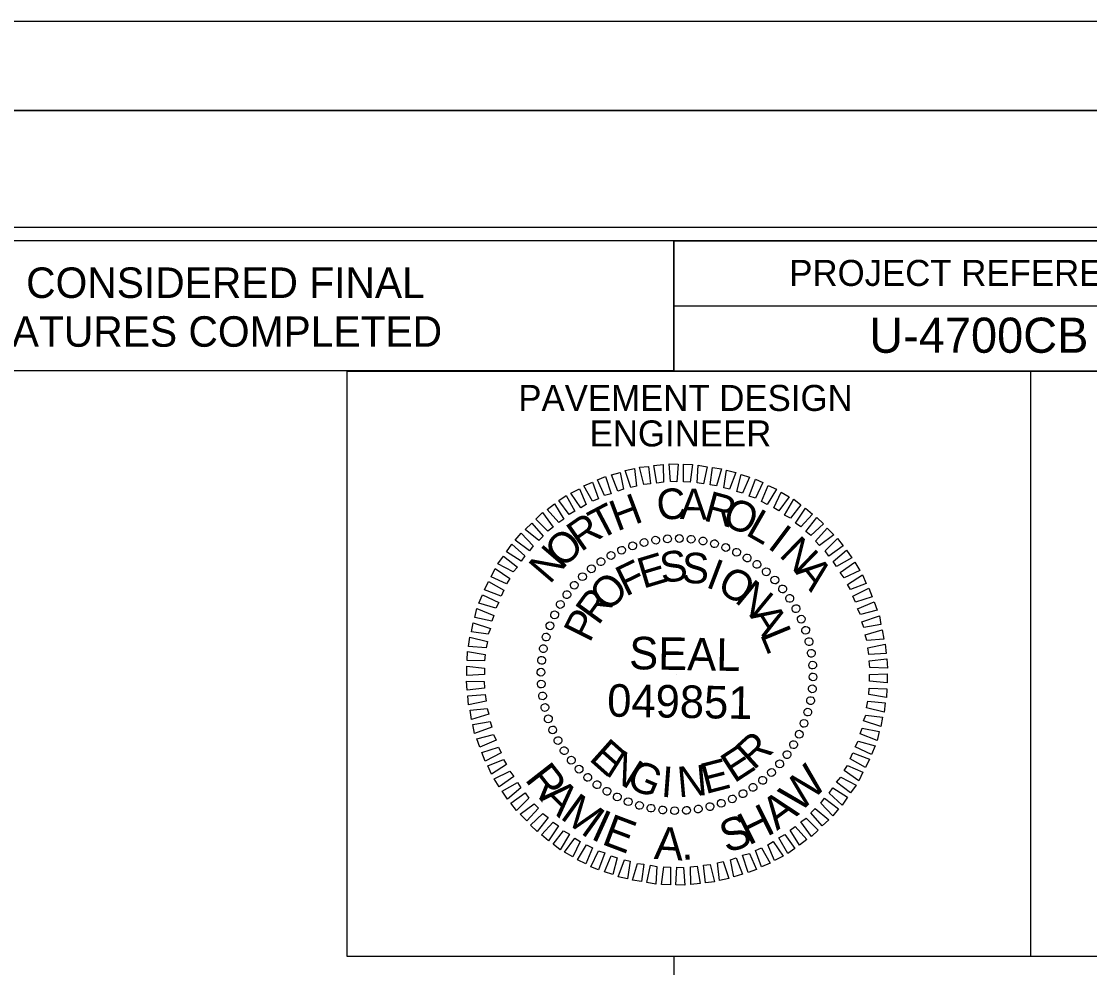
# Model space of a CAD drawing. Extents: x 2294455 to 2294795, y 719276 to 719941.
# Drawn here: x 2294722.83 to 2294763.9, y 719682.39 to 719718.76 of the extents above; entities that cross this region are included whole.
import ezdxf

# ---------------------------------------------------------------- set-up
doc = ezdxf.new("R2010")
doc.units = 0
for name, color, linetype in [('Default', 7, 'Continuous'), ('Old_Level_1', 7, 'Continuous'), ('Old_Level_2', 7, 'Continuous'), ('Sheet Data Field CELL', 7, 'Continuous'), ('Sheet Plan CELL', 7, 'Continuous'), ('Sheet Plot Border Inside CELL', 7, 'Continuous'), ('Sheet Plot Border Outside CELL', 7, 'Continuous'), ('Sheet Sticker Exception Certification CELL', 7, 'Continuous'), ('Sheet Typical CELL', 7, 'Continuous')]:
    doc.layers.add(name, color=color, linetype=linetype)

msp = doc.modelspace()

# ---------------------------------------------------------------- linework, layer by layer
at = {"layer": 'Default'}
msp.add_lwpolyline([(2294454.524, 719715.329), (2294794.524, 719715.329), (2294794.524, 719495.329), (2294454.524, 719495.329)], close=True, dxfattribs=at)
at = {"layer": 'Old_Level_1'}
msp.add_lwpolyline([(2294747.917, 719675.6), (2294787.924, 719675.6), (2294787.924, 719682.819), (2294747.917, 719682.819)], close=True, dxfattribs=at)
at = {"layer": 'Old_Level_2'}
for p, q in [((2294746.326, 719698.605), (2294746.326, 719698.605)), ((2294746.764, 719698.73), (2294746.764, 719698.73)), ((2294747.223, 719698.814), (2294747.223, 719698.814)), ((2294747.671, 719698.876), (2294747.671, 719698.876)), ((2294748.13, 719698.887), (2294748.13, 719698.887)), ((2294748.589, 719698.856), (2294748.589, 719698.856)), ((2294749.037, 719698.783), (2294749.037, 719698.783)), ((2294749.476, 719698.689), (2294749.476, 719698.689)), ((2294749.914, 719698.543), (2294749.914, 719698.543)), ((2294745.502, 719698.23), (2294745.502, 719698.23)), ((2294745.909, 719698.438), (2294745.909, 719698.438)), ((2294750.331, 719698.355), (2294750.331, 719698.355)), ((2294750.737, 719698.146), (2294750.737, 719698.146)), ((2294744.741, 719697.729), (2294744.741, 719697.729)), ((2294745.106, 719697.99), (2294745.106, 719697.99)), ((2294751.113, 719697.886), (2294751.113, 719697.886)), ((2294744.396, 719697.416), (2294744.396, 719697.416)), ((2294751.478, 719697.604), (2294751.478, 719697.604)), ((2294744.083, 719697.093), (2294744.083, 719697.093)), ((2294751.801, 719697.291), (2294751.801, 719697.291)), ((2294752.114, 719696.947), (2294752.114, 719696.947)), ((2294743.802, 719696.728), (2294743.802, 719696.728)), ((2294752.375, 719696.582), (2294752.375, 719696.582)), ((2294743.541, 719696.352), (2294743.541, 719696.352)), ((2294752.615, 719696.186), (2294752.615, 719696.186)), ((2294743.333, 719695.946), (2294743.333, 719695.946)), ((2294752.823, 719695.779), (2294752.823, 719695.779)), ((2294743.145, 719695.529), (2294743.145, 719695.529)), ((2294752.99, 719695.362), (2294752.99, 719695.362)), ((2294742.999, 719695.091), (2294742.999, 719695.091)), ((2294753.115, 719694.924), (2294753.115, 719694.924)), ((2294742.905, 719694.652), (2294742.905, 719694.652)), ((2294753.199, 719694.465), (2294753.199, 719694.465)), ((2294742.832, 719694.204), (2294742.832, 719694.204)), ((2294753.261, 719694.016), (2294753.261, 719694.016)), ((2294742.801, 719693.745), (2294742.801, 719693.745)), ((2294748.036, 719693.651), (2294748.036, 719693.651)), ((2294742.811, 719693.286), (2294742.811, 719693.286)), ((2294753.272, 719693.557), (2294753.272, 719693.557)), ((2294742.874, 719692.838), (2294742.874, 719692.838)), ((2294753.241, 719693.098), (2294753.241, 719693.098)), ((2294742.957, 719692.379), (2294742.957, 719692.379)), ((2294753.168, 719692.65), (2294753.168, 719692.65)), ((2294753.074, 719692.212), (2294753.074, 719692.212)), ((2294743.082, 719691.941), (2294743.082, 719691.941)), ((2294752.928, 719691.774), (2294752.928, 719691.774)), ((2294743.249, 719691.524), (2294743.249, 719691.524)), ((2294752.74, 719691.357), (2294752.74, 719691.357)), ((2294743.458, 719691.117), (2294743.458, 719691.117)), ((2294752.531, 719690.95), (2294752.531, 719690.95)), ((2294743.698, 719690.721), (2294743.698, 719690.721)), ((2294743.958, 719690.356), (2294743.958, 719690.356)), ((2294752.271, 719690.575), (2294752.271, 719690.575)), ((2294744.271, 719690.011), (2294744.271, 719690.011)), ((2294751.989, 719690.21), (2294751.989, 719690.21)), ((2294744.595, 719689.698), (2294744.595, 719689.698)), ((2294751.332, 719689.573), (2294751.332, 719689.573)), ((2294751.676, 719689.886), (2294751.676, 719689.886)), ((2294744.96, 719689.417), (2294744.96, 719689.417)), ((2294745.335, 719689.156), (2294745.335, 719689.156)), ((2294750.967, 719689.313), (2294750.967, 719689.313)), ((2294745.742, 719688.948), (2294745.742, 719688.948)), ((2294746.159, 719688.76), (2294746.159, 719688.76)), ((2294749.747, 719688.697), (2294749.747, 719688.697)), ((2294750.164, 719688.864), (2294750.164, 719688.864)), ((2294750.571, 719689.073), (2294750.571, 719689.073)), ((2294746.597, 719688.614), (2294746.597, 719688.614)), ((2294747.035, 719688.52), (2294747.035, 719688.52)), ((2294747.483, 719688.447), (2294747.483, 719688.447)), ((2294747.942, 719688.416), (2294747.942, 719688.416)), ((2294748.401, 719688.426), (2294748.401, 719688.426)), ((2294748.85, 719688.489), (2294748.85, 719688.489)), ((2294749.309, 719688.572), (2294749.309, 719688.572))]:
    msp.add_line(p, q, dxfattribs=at)
for points in [[(2294745.763, 719700.702), (2294745.523, 719701.327), (2294745.846, 719701.421), (2294745.982, 719700.775)], [(2294746.263, 719700.837), (2294746.044, 719701.494), (2294746.399, 719701.567), (2294746.482, 719700.889)], [(2294746.764, 719700.952), (2294746.597, 719701.619), (2294746.941, 719701.651), (2294747.014, 719700.983)], [(2294747.264, 719701.014), (2294747.15, 719701.682), (2294747.504, 719701.724), (2294747.515, 719701.046)], [(2294747.786, 719701.067), (2294747.734, 719701.745), (2294748.078, 719701.734), (2294748.036, 719701.056)], [(2294748.287, 719701.056), (2294748.287, 719701.734), (2294748.631, 719701.724), (2294748.537, 719701.046)], [(2294748.808, 719701.025), (2294748.85, 719701.703), (2294749.194, 719701.64), (2294749.058, 719700.983)], [(2294749.309, 719700.941), (2294749.402, 719701.609), (2294749.747, 719701.557), (2294749.559, 719700.91)], [(2294749.841, 719700.827), (2294749.945, 719701.505), (2294750.299, 719701.421), (2294750.06, 719700.775)], [(2294744.793, 719700.316), (2294744.459, 719700.9), (2294744.782, 719701.046), (2294745.022, 719700.41)], [(2294745.252, 719700.535), (2294744.98, 719701.14), (2294745.293, 719701.265), (2294745.512, 719700.597)], [(2294750.341, 719700.691), (2294750.498, 719701.338), (2294750.821, 719701.233), (2294750.56, 719700.618)], [(2294750.81, 719700.503), (2294751.05, 719701.16), (2294751.342, 719701.035), (2294751.05, 719700.43)], [(2294744.344, 719700.065), (2294743.958, 719700.629), (2294744.282, 719700.795), (2294744.542, 719700.191)], [(2294751.28, 719700.305), (2294751.541, 719700.921), (2294751.864, 719700.775), (2294751.509, 719700.191)], [(2294751.76, 719700.065), (2294752.041, 719700.66), (2294752.354, 719700.483), (2294751.958, 719699.94)], [(2294743.489, 719699.492), (2294743.041, 719699.992), (2294743.322, 719700.211), (2294743.687, 719699.627)], [(2294743.885, 719699.805), (2294743.499, 719700.337), (2294743.771, 719700.535), (2294744.115, 719699.93)], [(2294752.166, 719699.784), (2294752.531, 719700.389), (2294752.803, 719700.17), (2294752.396, 719699.659)], [(2294743.072, 719699.168), (2294742.613, 719699.627), (2294742.863, 719699.878), (2294743.27, 719699.314)], [(2294752.594, 719699.471), (2294752.98, 719700.045), (2294753.251, 719699.815), (2294752.792, 719699.325)], [(2294742.728, 719698.803), (2294742.196, 719699.231), (2294742.456, 719699.471), (2294742.895, 719698.97)], [(2294752.99, 719699.148), (2294753.418, 719699.69), (2294753.668, 719699.44), (2294753.188, 719698.991)], [(2294742.363, 719698.407), (2294741.82, 719698.814), (2294742.05, 719699.085), (2294742.509, 719698.595)], [(2294753.366, 719698.783), (2294753.814, 719699.273), (2294754.064, 719699.022), (2294753.522, 719698.616)], [(2294742.05, 719698.011), (2294741.487, 719698.365), (2294741.685, 719698.668), (2294742.185, 719698.209)], [(2294753.731, 719698.407), (2294754.21, 719698.876), (2294754.429, 719698.595), (2294753.877, 719698.198)], [(2294741.737, 719697.594), (2294741.153, 719697.906), (2294741.361, 719698.198), (2294741.904, 719697.781)], [(2294754.044, 719698), (2294754.555, 719698.438), (2294754.753, 719698.136), (2294754.169, 719697.802)], [(2294741.487, 719697.145), (2294740.892, 719697.406), (2294741.048, 719697.729), (2294741.612, 719697.343)], [(2294754.315, 719697.573), (2294754.868, 719697.969), (2294755.066, 719697.656), (2294754.461, 719697.364)], [(2294754.586, 719697.114), (2294755.17, 719697.479), (2294755.306, 719697.156), (2294754.711, 719696.916)], [(2294741.278, 719696.665), (2294740.631, 719696.905), (2294740.788, 719697.229), (2294741.382, 719696.895)], [(2294754.795, 719696.665), (2294755.41, 719696.978), (2294755.545, 719696.644), (2294754.899, 719696.436)], [(2294741.069, 719696.206), (2294740.423, 719696.394), (2294740.558, 719696.717), (2294741.184, 719696.425)], [(2294740.913, 719695.706), (2294740.266, 719695.841), (2294740.339, 719696.186), (2294740.996, 719695.925)], [(2294754.982, 719696.175), (2294755.618, 719696.446), (2294755.733, 719696.123), (2294755.087, 719695.956)], [(2294755.149, 719695.675), (2294755.817, 719695.914), (2294755.879, 719695.57), (2294755.222, 719695.456)], [(2294740.777, 719695.205), (2294740.131, 719695.289), (2294740.204, 719695.643), (2294740.861, 719695.424)], [(2294755.274, 719695.174), (2294755.931, 719695.372), (2294755.994, 719695.017), (2294755.337, 719694.955)], [(2294740.694, 719694.673), (2294740.026, 719694.736), (2294740.068, 719695.091), (2294740.746, 719694.924)], [(2294740.642, 719694.173), (2294739.964, 719694.194), (2294739.985, 719694.538), (2294740.663, 719694.423)], [(2294755.368, 719694.673), (2294756.046, 719694.819), (2294756.077, 719694.465), (2294755.41, 719694.423)], [(2294755.431, 719694.173), (2294756.109, 719694.256), (2294756.13, 719693.902), (2294755.452, 719693.922)], [(2294740.631, 719693.651), (2294739.953, 719693.62), (2294739.953, 719693.975), (2294740.631, 719693.902)], [(2294755.441, 719693.651), (2294756.119, 719693.683), (2294756.119, 719693.328), (2294755.441, 719693.401)], [(2294740.642, 719693.13), (2294739.964, 719693.046), (2294739.943, 719693.401), (2294740.621, 719693.38)], [(2294740.704, 719692.629), (2294740.026, 719692.483), (2294739.995, 719692.838), (2294740.663, 719692.879)], [(2294755.431, 719693.13), (2294756.109, 719693.109), (2294756.088, 719692.765), (2294755.41, 719692.879)], [(2294755.379, 719692.629), (2294756.046, 719692.567), (2294756.004, 719692.212), (2294755.326, 719692.379)], [(2294740.798, 719692.129), (2294740.141, 719691.93), (2294740.079, 719692.285), (2294740.736, 719692.348)], [(2294755.295, 719692.097), (2294755.942, 719692.014), (2294755.869, 719691.659), (2294755.212, 719691.878)], [(2294740.923, 719691.628), (2294740.256, 719691.388), (2294740.193, 719691.732), (2294740.85, 719691.847)], [(2294755.16, 719691.597), (2294755.806, 719691.461), (2294755.733, 719691.117), (2294755.076, 719691.378)], [(2294741.09, 719691.127), (2294740.454, 719690.856), (2294740.339, 719691.179), (2294740.986, 719691.346)], [(2294741.278, 719690.637), (2294740.663, 719690.324), (2294740.527, 719690.658), (2294741.174, 719690.867)], [(2294755.003, 719691.096), (2294755.65, 719690.908), (2294755.514, 719690.585), (2294754.888, 719690.877)], [(2294741.487, 719690.189), (2294740.902, 719689.824), (2294740.767, 719690.147), (2294741.361, 719690.387)], [(2294754.795, 719690.637), (2294755.441, 719690.397), (2294755.285, 719690.074), (2294754.69, 719690.408)], [(2294741.758, 719689.73), (2294741.205, 719689.333), (2294741.007, 719689.646), (2294741.612, 719689.938)], [(2294754.586, 719690.157), (2294755.18, 719689.897), (2294755.024, 719689.573), (2294754.461, 719689.959)], [(2294742.029, 719689.302), (2294741.518, 719688.864), (2294741.32, 719689.167), (2294741.904, 719689.5)], [(2294754.336, 719689.709), (2294754.92, 719689.396), (2294754.711, 719689.104), (2294754.169, 719689.521)], [(2294742.342, 719688.895), (2294741.862, 719688.426), (2294741.643, 719688.708), (2294742.196, 719689.104)], [(2294754.023, 719689.292), (2294754.586, 719688.937), (2294754.388, 719688.635), (2294753.887, 719689.094)], [(2294742.707, 719688.52), (2294742.258, 719688.03), (2294742.008, 719688.28), (2294742.55, 719688.687)], [(2294753.71, 719688.895), (2294754.252, 719688.489), (2294754.023, 719688.217), (2294753.564, 719688.708)], [(2294743.082, 719688.155), (2294742.655, 719687.613), (2294742.404, 719687.863), (2294742.884, 719688.311)], [(2294753.345, 719688.499), (2294753.877, 719688.071), (2294753.616, 719687.832), (2294753.178, 719688.332)], [(2294743.479, 719687.832), (2294743.093, 719687.258), (2294742.822, 719687.487), (2294743.28, 719687.978)], [(2294753.001, 719688.134), (2294753.46, 719687.675), (2294753.209, 719687.425), (2294752.803, 719687.988)], [(2294743.906, 719687.519), (2294743.541, 719686.914), (2294743.27, 719687.133), (2294743.677, 719687.644)], [(2294752.187, 719687.498), (2294752.573, 719686.966), (2294752.302, 719686.768), (2294751.958, 719687.373)], [(2294752.583, 719687.811), (2294753.032, 719687.31), (2294752.75, 719687.091), (2294752.385, 719687.675)], [(2294744.313, 719687.237), (2294744.031, 719686.643), (2294743.718, 719686.82), (2294744.115, 719687.362)], [(2294744.793, 719686.997), (2294744.532, 719686.382), (2294744.209, 719686.528), (2294744.563, 719687.112)], [(2294751.728, 719687.237), (2294752.114, 719686.674), (2294751.791, 719686.507), (2294751.53, 719687.112)], [(2294745.262, 719686.799), (2294745.022, 719686.142), (2294744.73, 719686.267), (2294745.022, 719686.872)], [(2294745.731, 719686.611), (2294745.575, 719685.965), (2294745.252, 719686.069), (2294745.512, 719686.684)], [(2294750.821, 719686.768), (2294751.092, 719686.163), (2294750.779, 719686.038), (2294750.56, 719686.705)], [(2294751.28, 719686.987), (2294751.614, 719686.403), (2294751.29, 719686.257), (2294751.05, 719686.893)], [(2294746.232, 719686.476), (2294746.128, 719685.798), (2294745.773, 719685.881), (2294746.013, 719686.528)], [(2294746.764, 719686.361), (2294746.67, 719685.694), (2294746.326, 719685.746), (2294746.514, 719686.392)], [(2294747.264, 719686.278), (2294747.223, 719685.6), (2294746.879, 719685.662), (2294747.014, 719686.319)], [(2294747.786, 719686.246), (2294747.786, 719685.568), (2294747.442, 719685.579), (2294747.536, 719686.257)], [(2294748.287, 719686.236), (2294748.339, 719685.558), (2294747.995, 719685.568), (2294748.036, 719686.246)], [(2294748.808, 719686.288), (2294748.923, 719685.621), (2294748.568, 719685.579), (2294748.558, 719686.257)], [(2294749.309, 719686.351), (2294749.476, 719685.683), (2294749.131, 719685.652), (2294749.058, 719686.319)], [(2294749.809, 719686.465), (2294750.028, 719685.808), (2294749.674, 719685.735), (2294749.59, 719686.413)], [(2294750.31, 719686.601), (2294750.55, 719685.975), (2294750.226, 719685.881), (2294750.091, 719686.528)]]:
    msp.add_lwpolyline(points, close=True, dxfattribs=at)
for centre, major_axis in [((2294747.218, 719698.818), (-0.023, 0.148)), ((2294747.671, 719698.87), (-0.01, 0.15)), ((2294748.128, 719698.882), (0.003, 0.15)), ((2294748.583, 719698.854), (0.016, 0.149)), ((2294749.034, 719698.787), (0.029, 0.147)), ((2294745.908, 719698.43), (-0.061, 0.137)), ((2294746.333, 719698.598), (-0.049, 0.142)), ((2294746.771, 719698.727), (-0.036, 0.146)), ((2294749.478, 719698.68), (0.041, 0.144)), ((2294749.911, 719698.535), (0.054, 0.14)), ((2294745.111, 719697.988), (-0.084, 0.125)), ((2294745.5, 719698.227), (-0.073, 0.131)), ((2294750.33, 719698.353), (0.066, 0.135)), ((2294750.731, 719698.135), (0.077, 0.129)), ((2294744.744, 719697.717), (-0.095, 0.117)), ((2294751.111, 719697.884), (0.088, 0.122)), ((2294751.468, 719697.599), (0.099, 0.113)), ((2294744.402, 719697.414), (-0.104, 0.108)), ((2294751.799, 719697.285), (0.108, 0.104)), ((2294743.804, 719696.726), (-0.122, 0.088)), ((2294744.088, 719697.083), (-0.113, 0.099)), ((2294752.102, 719696.943), (0.117, 0.095)), ((2294743.552, 719696.346), (-0.129, 0.077)), ((2294752.373, 719696.577), (0.125, 0.084)), ((2294743.334, 719695.945), (-0.135, 0.066)), ((2294752.612, 719696.187), (0.131, 0.073)), ((2294743.152, 719695.526), (-0.14, 0.054)), ((2294752.815, 719695.779), (0.137, 0.061)), ((2294743.007, 719695.093), (-0.144, 0.041)), ((2294752.983, 719695.354), (0.142, 0.049)), ((2294753.112, 719694.917), (0.146, 0.036)), ((2294742.901, 719694.649), (-0.147, 0.029)), ((2294753.203, 719694.47), (0.148, 0.023)), ((2294742.833, 719694.198), (-0.149, 0.016)), ((2294753.255, 719694.016), (0.15, 0.01)), ((2294742.806, 719693.743), (-0.15, 0.003)), ((2294753.267, 719693.56), (0.15, -0.003)), ((2294742.818, 719693.286), (-0.15, -0.01)), ((2294753.239, 719693.104), (0.149, -0.016)), ((2294742.869, 719692.833), (-0.148, -0.023)), ((2294753.172, 719692.653), (0.147, -0.029)), ((2294742.96, 719692.386), (-0.146, -0.036)), ((2294753.065, 719692.209), (0.144, -0.041)), ((2294743.09, 719691.948), (-0.142, -0.049)), ((2294743.257, 719691.523), (-0.137, -0.061)), ((2294752.92, 719691.776), (0.14, -0.054)), ((2294743.461, 719691.115), (-0.131, -0.073)), ((2294752.738, 719691.358), (0.135, -0.066)), ((2294743.699, 719690.726), (-0.125, -0.084)), ((2294752.269, 719690.576), (0.122, -0.088)), ((2294752.52, 719690.957), (0.129, -0.077)), ((2294743.971, 719690.359), (-0.117, -0.095)), ((2294751.984, 719690.219), (0.113, -0.099)), ((2294744.273, 719690.017), (-0.108, -0.104)), ((2294751.67, 719689.888), (0.104, -0.108)), ((2294744.604, 719689.703), (-0.099, -0.113)), ((2294744.961, 719689.419), (-0.088, -0.122)), ((2294751.328, 719689.586), (0.095, -0.117)), ((2294745.342, 719689.167), (-0.077, -0.129)), ((2294745.743, 719688.949), (-0.066, -0.135)), ((2294750.572, 719689.076), (0.073, -0.131)), ((2294750.962, 719689.314), (0.084, -0.125)), ((2294746.161, 719688.767), (-0.054, -0.14)), ((2294746.594, 719688.622), (-0.041, -0.144)), ((2294747.038, 719688.516), (-0.029, -0.147)), ((2294749.302, 719688.575), (0.036, -0.146)), ((2294749.739, 719688.705), (0.049, -0.142)), ((2294750.164, 719688.872), (0.061, -0.137)), ((2294747.489, 719688.448), (-0.016, -0.149)), ((2294747.945, 719688.421), (-0.003, -0.15)), ((2294748.401, 719688.433), (0.01, -0.15)), ((2294748.855, 719688.484), (0.023, -0.148))]:
    msp.add_ellipse(centre, major_axis=major_axis, ratio=0.999708, dxfattribs=at)
at = {"layer": 'Sheet Plan CELL'}
for points in [[(2294761.64, 719682.819), (2294735.355, 719682.819), (2294735.355, 719705.319), (2294761.64, 719705.319)], [(2294787.924, 719682.819), (2294761.64, 719682.819), (2294761.64, 719705.319), (2294787.924, 719705.319)]]:
    msp.add_lwpolyline(points, dxfattribs=at)
at = {"layer": 'Sheet Plot Border Inside CELL'}
msp.add_lwpolyline([(2294790.424, 719710.839), (2294457.124, 719710.839), (2294457.124, 719499.819), (2294790.424, 719499.819)], close=True, dxfattribs=at)
at = {"layer": 'Sheet Plot Border Outside CELL'}
for points in [[(2294793.79, 719718.758), (2294456.99, 719718.758), (2294456.99, 719498.758), (2294793.79, 719498.758)], [(2294794.524, 719715.329), (2294454.524, 719715.329), (2294454.524, 719495.329), (2294794.524, 719495.329)]]:
    msp.add_lwpolyline(points, close=True, dxfattribs=at)
at = {"layer": 'Sheet Sticker Exception Certification CELL'}
for p, q in [((2294705.291, 719710.332), (2294747.914, 719710.332)), ((2294747.914, 719710.329), (2294747.914, 719705.322)), ((2294747.914, 719705.325), (2294705.291, 719705.325))]:
    msp.add_line(p, q, dxfattribs=at)
at = {"layer": 'Sheet Typical CELL'}
msp.add_line((2294747.914, 719707.819), (2294787.924, 719707.819), dxfattribs=at)
for points in [[(2294787.924, 719710.329), (2294487.924, 719710.329), (2294487.924, 719500.329), (2294787.924, 719500.329)], [(2294747.914, 719710.329), (2294787.924, 719710.329), (2294787.924, 719705.319), (2294747.914, 719705.319)]]:
    msp.add_lwpolyline(points, close=True, dxfattribs=at)

# ---------------------------------------------------------------- texts
at = {"layer": 'Default'}
for s, rotation, p in [('R', 308.005, (2294742.156, 719689.619)), ('W', 45.0672, (2294752.745, 719688.29)), ('A', 315.3996, (2294742.722, 719688.896)), ('M', 324.1387, (2294743.503, 719688.143)), ('A', 36.3281, (2294751.878, 719687.637)), ('I', 335.5363, (2294744.678, 719687.355)), ('E', 339.2947, (2294745.096, 719687.149)), ('H', 26.4584, (2294750.793, 719687.067)), ('S', 19.2166, (2294749.944, 719686.772)), ('A', 356.4062, (2294747.135, 719686.57)), ('.', 5.1454, (2294748.218, 719686.515))]:
    msp.add_text(s, height=1.251, rotation=rotation, dxfattribs=at).set_placement(p)
at = {"layer": 'Old_Level_2'}
for s, height, rotation, p in [('H', 1.176, 20.6195, (2294745.731, 719699.148)), ('C', 1.176, 6.2199, (2294747.317, 719699.565)), ('A', 1.176, 359.0203, (2294748.141, 719699.627)), ('R', 1.176, 344.6211, (2294749.017, 719699.586)), ('T', 1.176, 27.8198, (2294745.053, 719698.803)), ('O', 1.176, 337.4212, (2294749.715, 719699.429)), ('R', 1.176, 35.0205, (2294744.344, 719698.344)), ('L', 1.176, 330.2209, (2294750.633, 719699.043)), ('I', 1.176, 323.0201, (2294751.478, 719698.543)), ('O', 1.176, 42.2217, (2294743.625, 719697.698)), ('N', 1.176, 315.8189, (2294751.926, 719698.219)), ('N', 1.176, 49.4235, (2294743.145, 719697.093)), ('E', 1.176, 16.6111, (2294746.733, 719696.947)), ('S', 1.176, 7.2556, (2294747.452, 719697.166)), ('S', 1.176, 357.9004, (2294748.203, 719697.176)), ('F', 1.176, 25.967, (2294746.065, 719696.634)), ('I', 1.176, 339.1896, (2294749.1, 719697.03)), ('O', 1.176, 329.8335, (2294749.517, 719696.884)), ('A', 1.176, 308.6172, (2294752.542, 719697.604)), ('O', 1.176, 44.6812, (2294745.377, 719696.019)), ('R', 1.176, 54.0397, (2294745.012, 719695.508)), ('N', 1.176, 320.4766, (2294750.216, 719696.467)), ('P', 1.176, 63.3989, (2294744.678, 719694.84)), ('A', 1.176, 301.7603, (2294750.81, 719695.925)), ('L', 1.176, 292.4009, (2294751.217, 719695.205)), ('SEAL', 1.2512, 359, (2294746.19, 719693.86)), ('049851', 1.2515, 359, (2294745.345, 719692.038)), ('E', 1.176, 318.2769, (2294744.615, 719690.387)), ('R', 1.176, 42.4814, (2294750.977, 719689.949)), ('N', 1.176, 327.634, (2294745.241, 719689.824)), ('E', 1.176, 33.1241, (2294750.237, 719689.459)), ('E', 1.176, 14.4118, (2294749.131, 719689.052)), ('G', 1.176, 336.9902, (2294746.034, 719689.354)), ('I', 1.176, 355.7012, (2294747.4, 719688.958)), ('N', 1.176, 5.0564, (2294748.099, 719688.927))]:
    msp.add_text(s, height=height, rotation=rotation, dxfattribs=at).set_placement(p)
at = {"layer": 'Sheet Data Field CELL'}
msp.add_text('U-4700CB', height=1.35, rotation=360, dxfattribs=at).set_placement((2294755.427, 719706.02))
at = {"layer": 'Sheet Plan CELL'}
for s, height, p in [('PAVEMENT DESIGN', 1.00002, (2294741.936, 719703.784)), ('ENGINEER', 1, (2294744.678, 719702.42))]:
    msp.add_text(s, height=height, dxfattribs=at).set_placement(p)
at = {"layer": 'Sheet Sticker Exception Certification CELL'}
for s, p in [('DOCUMENT NOT CONSIDERED FINAL', (2294709.781, 719708.128)), ('UNLESS ALL SIGNATURES COMPLETED', (2294708.7, 719706.252))]:
    msp.add_text(s, height=1.17193, dxfattribs=at).set_placement(p)
at = {"layer": 'Sheet Typical CELL'}
msp.add_text('PROJECT REFERENCE NO.', height=1.00002, dxfattribs=at).set_placement((2294752.354, 719708.589))

doc.saveas('drawing.dxf')
